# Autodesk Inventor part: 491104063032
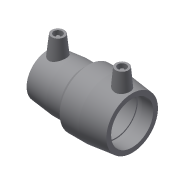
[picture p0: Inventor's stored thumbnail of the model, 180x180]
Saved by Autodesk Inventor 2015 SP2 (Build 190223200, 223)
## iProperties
Created: 2017-06
Part Number: 491104063032
Material: Generic
Description: PLASSON REDUCING COUPLER 63-32
Document SubType Name: Modeling
Designer: KIM
Mass: 54.8237 g
Surface Area: 155.252 cm^2
Volume: 54.8237 cm^3
Density: 1 g/cm^3
Appearance: Default
Author: KIM
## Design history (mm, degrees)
derived "491104.ipt"
feature "Solid1::491104.ipt"
tag "TaggingFeature1"
body "Solid1"
other parameters: "d0" = 119, "d2" = 45, "d4" = 24, "d5" = 40.5, "d7" = 32, "d8" = 168 deg, "d10" = 16, "d11" = 5.33333, "d13" = 119, "d14" = 17.6296, "d18" = 32, "d19" = 2, "d20" = 168 deg, "d22" = 108.92847, "d25" = 135 deg, "d29" = 45, "d30" = 15, "d31" = 45.22, "d34" = 6 deg, "d35" = 15, "d38" = 27.4, "d39" = 5 deg, "d41" = 4, "d42" = 14, "d43" = 0, "d45" = 4, "d46" = 14, "d47" = 0, "d48" = 45, "d49" = 63, "d50" = 82, "d52" = 28.8, "d53" = 22.8, "d54" = 7.6, "d55" = 168 deg, "d56" = 34.2, "d57" = 57, "d58" = 73.8, "d59" = 2, "d60" = 135 deg, "d61" = 59, "d62" = 15, "d64" = 4, "d66" = 5 deg, "d67" = 14, "d68" = 0, "d69" = 45.22, "d70" = 45, "d71" = 82, "d73" = 77.08, "d76" = 2, "d77" = 168 deg, "d78" = 63, "d79" = 2, "d80" = 57, "d81" = 28.8, "d82" = 42.3, "d83" = 120 deg, "d88" = 15, "d89" = 24.35, "d90" = 5 deg, "d92" = 4, "d93" = 14, "d94" = 0, "d95" = 3, "d96" = 0, "d97" = 3, "d98" = 0, "d99" = 11.6, "d100" = 2.9, "d101" = 41.031, "d102" = 20 deg, "d103" = 16.53, "d104" = 4.1325, "d105" = 74.7676, "d106" = 3.60705, "d107" = 3, "d108" = 0, "d109" = 3, "d110" = 0, "d_1" = 32, "L_" = 119, "D_1" = 45, "A_1" = 45, "d_2" = 12, "L_1" = 57, "d_" = 63, "A_" = 59, "D_" = 82
